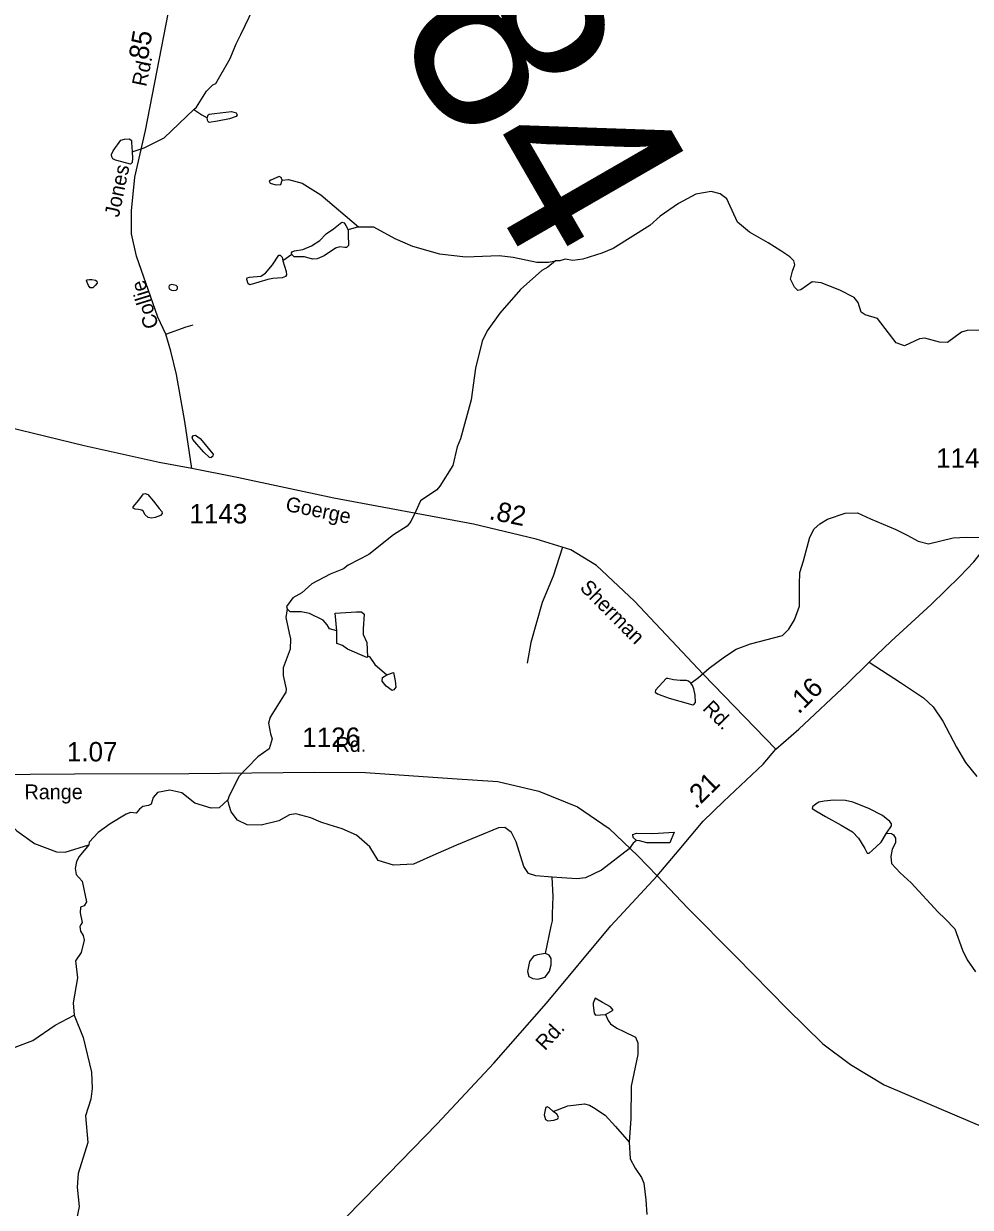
# Model space of a CAD drawing. Extents: x 2056842 to 2160602, y 826753 to 1016856.
# Drawn here: x 2065901 to 2071991, y 926037 to 933655 of the extents above; entities that cross this region are included whole.
import ezdxf

# ---------------------------------------------------------------- set-up
doc = ezdxf.new("R2010")
doc.units = 0
for name, color, linetype in [('Exist Hydrographic Creek Single Shore', 7, 'Continuous'), ('Exist Hydrographic Misc Water Feature', 7, 'Continuous'), ('Exist Road Non-System Type 51', 7, 'Continuous'), ('Exist Road Secondary Mileage Hundredths English Label', 7, 'Continuous'), ('Exist Road Secondary Structure Standard Bridge Number Label', 7, 'Continuous'), ('Exist Road Secondary Type 51 Attributed', 7, 'Continuous'), ('Exist Road Secondary Type 51 Label', 7, 'Continuous'), ('Exist Road Secondary Type 51 Number Label', 7, 'Continuous')]:
    doc.layers.add(name, color=color, linetype=linetype)

msp = doc.modelspace()

# ---------------------------------------------------------------- linework, layer by layer
at = {"layer": 'Exist Hydrographic Creek Single Shore'}
for points in [[(2072086.4, 931682.3), (2071970.5, 931680.1), (2071934.5, 931668.1), (2071844.5, 931602), (2071792.7, 931605.7), (2071698.7, 931629.7), (2071664.5, 931625.8), (2071566.8, 931581.5), (2071514.7, 931601.3), (2071394.2, 931757.1), (2071314.3, 931781), (2071288.4, 931797), (2071270.1, 931861), (2071244.1, 931892.7), (2071150.7, 931938.6), (2071031.8, 931986), (2070974.2, 931992.4), (2070901.4, 931940.5), (2070880.9, 931936.7), (2070859.2, 931959.7), (2070833.8, 932010.2), (2070846.4, 932061.5), (2070863, 932101.8), (2070856.6, 932128), (2070831.1, 932154.9), (2070772.2, 932193.3), (2070691.6, 932244.5), (2070571.4, 932313.6), (2070493.3, 932377.6), (2070435.2, 932503.4), (2070424.8, 932527.3), (2070380.9, 932559.4), (2070324.7, 932575), (2070224.9, 932557), (2070113.1, 932496.7), (2069995.3, 932416.4), (2069929.4, 932356.4), (2069693.7, 932208.1), (2069621.5, 932177.7), (2069497.7, 932139.6), (2069433.8, 932131.4), (2069385.8, 932139.3), (2069349.8, 932127.2), (2069321.9, 932127.2)], [(2069321.9, 932127.2), (2069273.8, 932087.1), (2069234, 932067), (2069098.2, 931942.8), (2068964.4, 931790.7), (2068882.7, 931678.5), (2068850.8, 931610.3), (2068807.2, 931438.2), (2068779.3, 931234.4), (2068712.1, 930982.1), (2068690, 930930.1), (2068662.2, 930810.2), (2068578.5, 930678.1), (2068558.6, 930653.9), (2068454.8, 930583.8), (2068424.8, 930517.5), (2068392.9, 930449.6), (2068369, 930421.5), (2068281.2, 930365.3), (2068121.4, 930239), (2067989.4, 930168.9), (2067959.7, 930144.9), (2067873.7, 930112.5), (2067755.6, 930048.4), (2067689.8, 929992.3), (2067632, 929960), (2067592.1, 929904.1), (2067596, 929888.3)], [(2070194, 929410.5), (2070242.6, 929446.3), (2070310.8, 929507.3), (2070410.2, 929579.4), (2070484.4, 929629.4), (2070577.8, 929663.9), (2070783.1, 929717.1), (2070822.7, 929758), (2070859.8, 929818.2), (2070893.1, 929905.2), (2070893.1, 930044.7), (2070893.6, 930122.4), (2070917.4, 930198.5), (2070959.2, 930350.5), (2070987.1, 930402.6), (2071023, 930436.6), (2071072.8, 930464.7), (2071186.7, 930503.6), (2071264.7, 930506.2), (2071349.2, 930467.8), (2071512.9, 930398.7), (2071585.8, 930361.6), (2071656.2, 930323.2), (2071722.5, 930307.8), (2071881.1, 930344.9), (2071965.5, 930348.8), (2072219.2, 930342.8)], [(2067596, 929888.3), (2067588, 929832), (2067608.2, 929732.1), (2067618.3, 929696.2), (2067616.6, 929628.3), (2067570.8, 929508.1), (2067570.8, 929460.2), (2067590.9, 929372.2), (2067586.9, 929352.3), (2067487.4, 929191.9), (2067475.5, 929151.8), (2067489.5, 929083.9), (2067499.6, 929051.8), (2067481.6, 928987.9), (2067407.6, 928936), (2067337.9, 928863.6), (2067285.9, 928809.5), (2067222.2, 928679.6), (2067214.2, 928659.4)], [(2067214.2, 928659.4), (2067158.3, 928607.4), (2067106.5, 928605.2), (2067002.2, 928637.4), (2066919, 928705.2), (2066841, 928720.6), (2066762.9, 928706.5), (2066733.5, 928674.5), (2066722, 928632.2), (2066704.1, 928623.3), (2066668.3, 928616.9), (2066646.5, 928599), (2066624.8, 928573.4), (2066589, 928578.5), (2066560.8, 928567), (2066458.2, 928504.2), (2066380.7, 928449.9), (2066322.9, 928385.8), (2066320.9, 928369.8)], [(2065452.5, 928668.4), (2065560.6, 928664.6), (2065672.7, 928632.7), (2065716.6, 928604.8), (2065856.9, 928459.1), (2065971.1, 928379.3), (2066113.2, 928325.5), (2066169.2, 928321.6), (2066321.1, 928370)], [(2066320.9, 928369.8), (2066259, 928293.6), (2066241.3, 928261.5), (2066233.1, 928217.7), (2066239.7, 928179.1), (2066278.1, 928135.6), (2066305, 928003.7), (2066289.6, 927976.9), (2066266.6, 927969.2), (2066264, 927932.1), (2066278.1, 927869.3), (2066270.4, 927859.1), (2066262.7, 927843.7), (2066266.6, 927813), (2066284.5, 927786.1), (2066290.9, 927755.4), (2066270.4, 927677.3), (2066234.6, 927623.6), (2066248.4, 927513.9), (2066218.8, 927353.7), (2066227, 927273.8)], [(2066227, 927273.8), (2066283.1, 927129.9), (2066337.5, 926905.9), (2066341.9, 926801.8), (2066334, 926733.7), (2066298.2, 926625.9), (2066314.4, 926453.9), (2066252.8, 926253.7), (2066245.1, 926165.6), (2066257.3, 926041.6), (2066231.6, 925913.9)]]:
    msp.add_lwpolyline(points, dxfattribs=at)
at = {"layer": 'Exist Hydrographic Misc Water Feature'}
for p, q in [((2068055.7, 932347.1), (2067988.5, 932327.7)), ((2067626.5, 932169), (2067568.9, 932128))]:
    msp.add_line(p, q, dxfattribs=at)
for points in [[(2066996.4, 933101.1), (2067012.4, 933117.1), (2067078, 933221.1), (2067118, 933261.2), (2067138, 933269.3), (2067229.7, 933429.5), (2067267.4, 933525.5), (2067299.4, 933585.6), (2067379, 933753.8)], [(2066598.7, 932829.1), (2066676.7, 932856.5), (2066804.6, 932920.6), (2066996.4, 933101.1)], [(2066996.4, 933101.1), (2067047.9, 933066.9), (2067082.6, 933049.5)], [(2067082.6, 933049.5), (2067088.4, 933066.9), (2067094.2, 933072.7), (2067129, 933075.6), (2067237.7, 933088.6), (2067268.1, 933079.9), (2067273.9, 933066.9), (2067268.1, 933056.7), (2067226.1, 933042.2), (2067147.8, 933026.3), (2067094.2, 933019.1), (2067087, 933027.7), (2067084.1, 933036.4), (2067082.6, 933049.5)], [(2066598.7, 932829.1), (2066601.6, 932788.5), (2066600.2, 932761), (2066588.6, 932750.8), (2066565.4, 932756.6), (2066492.9, 932776.9), (2066474.1, 932785.6), (2066468.3, 932797.2), (2066466.9, 932813.2), (2066477, 932836.4), (2066526.3, 932904.5), (2066549.4, 932911.8), (2066582.8, 932913.2), (2066594.4, 932903.1), (2066594.4, 932890), (2066598.7, 932829.1)], [(2067565.2, 932648.1), (2067557, 932664.1), (2067545.1, 932672), (2067491.1, 932648)], [(2067565.2, 932648.1), (2067605, 932652.2), (2067693.1, 932628.3), (2067813.3, 932552.6), (2068055.7, 932347.1)], [(2067491.1, 932648), (2067481.1, 932640), (2067487, 932628), (2067523.1, 932618.1)], [(2067523.1, 932618.1), (2067555.1, 932620.1), (2067565.2, 932648.1)], [(2067626.5, 932169), (2067625.2, 932180.5), (2067629, 932186.9), (2067643.1, 932192), (2067696.8, 932201), (2067753.1, 932225.3), (2067805.6, 932258.6), (2067846.5, 932302.1), (2067893.8, 932334.1), (2067948.8, 932376.4), (2067962.9, 932372.5), (2067973.1, 932354.6), (2067988.5, 932327.7)], [(2068055.7, 932347.1), (2068151.6, 932347.2), (2068289.8, 932271.6), (2068401.8, 932221.7), (2068575.9, 932174.1), (2068745.9, 932154.4), (2068959.9, 932162.8), (2069050, 932150.9), (2069202.1, 932119.2), (2069278, 932119.3), (2069322.1, 932127.4)], [(2067988.5, 932327.7), (2067988.5, 932297), (2067991.1, 932227.9), (2067978.3, 932213.8), (2067968, 932213.8), (2067934.8, 932217.6), (2067907.9, 932210), (2067835, 932161.3), (2067790.2, 932140.8), (2067759.5, 932139.6), (2067707.1, 932153.6), (2067675.1, 932154.9), (2067640.5, 932154.9), (2067632.9, 932162.6), (2067626.5, 932169)], [(2067568.9, 932128), (2067589.4, 932058.9), (2067591.9, 932037.2), (2067585.5, 932028.2), (2067565.1, 932018), (2067504.9, 932014.1), (2067471.7, 932009), (2067356.5, 931973.2), (2067345, 931980.8), (2067336.1, 932009), (2067339.9, 932019.2), (2067354, 932023.1), (2067426.9, 932029.5), (2067457.6, 932048.7), (2067501.1, 932102.4), (2067542, 932163.9), (2067551, 932163.9), (2067563.8, 932151.1), (2067568.9, 932128)], [(2066339.6, 932008), (2066364.4, 932003.9), (2066372.6, 931997.7), (2066373.6, 931985.3), (2066362.3, 931969.8), (2066345.8, 931955.4), (2066329.3, 931955.4), (2066317.9, 931968.8), (2066312.7, 931984.3), (2066306.5, 931999.8), (2066310.7, 932004.9), (2066324.1, 932008), (2066339.6, 932008)], [(2066862.9, 931974), (2066852.6, 931976), (2066837.1, 931969.8), (2066835, 931960.5), (2066838.1, 931947.1), (2066851.6, 931939.9), (2066865, 931936.8), (2066882.5, 931939.9), (2066891.8, 931948.1), (2066890.8, 931960.5), (2066881.5, 931968.8), (2066862.9, 931974)], [(2067059.7, 930956.3), (2067096.1, 930911.9), (2067120.1, 930883.4), (2067117.5, 930871.9), (2067105, 930859.4), (2067097, 930863), (2067059.7, 930896.8), (2067014.4, 930947.4), (2066988.6, 930977.7), (2066986, 930992.8), (2066994, 931003.4), (2067006.4, 931006.1), (2067036.6, 930984.8), (2067059.7, 930956.3)], [(2066736.2, 930581.7), (2066773.5, 930533.7), (2066789.5, 930515.9), (2066792.1, 930501.7), (2066780.6, 930489.2), (2066747.7, 930476.8), (2066723.7, 930471.4), (2066702.4, 930476.8), (2066681.1, 930496.3), (2066671.3, 930515.9), (2066662.4, 930523.9), (2066640.2, 930528.3), (2066618, 930530.1), (2066604.7, 930537.2), (2066604.7, 930544.3), (2066641.1, 930587), (2066673.1, 930628.8), (2066683.7, 930630.6), (2066700.6, 930623.4), (2066736.2, 930581.7)], [(2067916.4, 929747), (2067868.4, 929760.8), (2067854.5, 929784.8), (2067828.3, 929814.7), (2067740.3, 929858.5), (2067686.4, 929868.4), (2067616.2, 929868.3), (2067596.1, 929888.2)], [(2067916.4, 929747), (2067904.3, 929860.9), (2068042.1, 929869.1)], [(2068042.1, 929869.1), (2068074.1, 929869.2), (2068092.4, 929855.2), (2068084.4, 929759.3), (2068084.6, 929723.3), (2068108.6, 929671.2), (2068112.9, 929579.3)], [(2068112.9, 929579.3), (2068108.8, 929575.3), (2067984.7, 929629), (2067952.7, 929652.9), (2067916.6, 929664.9), (2067916.4, 929747)], [(2068112.9, 929579.3), (2068124.8, 929583.3), (2068160.8, 929531.3), (2068236.9, 929463.5)], [(2068233, 929391.5), (2068207, 929423.5), (2068209, 929447.5), (2068236.9, 929463.5)], [(2068236.9, 929463.5), (2068281, 929479.6), (2068291.1, 929425.6)], [(2068291.1, 929425.6), (2068295, 929383.6), (2068283.1, 929367.6), (2068271.2, 929363.6), (2068233, 929391.5)], [(2070194, 929410.5), (2070178.6, 929423.3), (2070165.8, 929427.1), (2070123.6, 929427.1), (2070081.4, 929431), (2070045.6, 929441.2), (2070035.3, 929439.9), (2069965, 929365.7), (2069963.7, 929352.9), (2069979.1, 929341.4), (2070007.2, 929329.8), (2070054.5, 929313.2), (2070176.1, 929278.6), (2070204.2, 929271), (2070213.2, 929273.5), (2070223.4, 929286.3), (2070220.8, 929333.7), (2070213.2, 929374.6), (2070204.2, 929395.1), (2070194, 929410.5)], [(2069300.2, 928160.5), (2069195.3, 928169.4), (2069149.2, 928185.2), (2069119.3, 928229.3), (2069070, 928389.7), (2069040.5, 928448.5), (2068995.8, 928480.6), (2068956.1, 928479.3), (2068686.2, 928366.6), (2068532.7, 928301.3), (2068409.9, 928245), (2068279.4, 928238.6), (2068180.9, 928269.3), (2068127.3, 928357.7), (2068042.9, 928431.2), (2067950.9, 928473.1), (2067866.3, 928498.5), (2067812.6, 928516.4), (2067748.6, 928543.3), (2067651.1, 928569.5), (2067611.5, 928563.1), (2067543.7, 928524.7), (2067429.8, 928496.6), (2067339, 928497.8), (2067276.3, 928528.6), (2067236.6, 928581), (2067222.5, 928623.7), (2067214.5, 928659.7)], [(2071452.8, 928445.5), (2071483.1, 928492.7), (2071484.4, 928505.5), (2071472.8, 928520.8), (2071425.5, 928558), (2071337.2, 928602.8), (2071234.9, 928643.7), (2071187.6, 928654), (2071113.4, 928656.5), (2071050.7, 928651.4), (2071017.4, 928645), (2070999.5, 928633.5), (2070975.2, 928614.3), (2070973.9, 928604), (2070997, 928587.4), (2071059.6, 928551.6), (2071160.7, 928496.5), (2071233.6, 928454.3), (2071272, 928412), (2071311.7, 928346.7), (2071328.3, 928316), (2071339.8, 928316), (2071359, 928332.7), (2071416.6, 928387.7), (2071452.8, 928445.5)], [(2069842.7, 928396.6), (2069823, 928380.5), (2069797, 928344.5), (2069619.2, 928206.1), (2069515.2, 928157.9), (2069459.2, 928149.8), (2069363.3, 928157.7), (2069300.2, 928160.5)], [(2069842.7, 928396.6), (2069822.8, 928416.5), (2069820.7, 928436.5), (2069844.7, 928444.6), (2069948.7, 928442.7)], [(2069951, 928382.7), (2069911, 928382.6), (2069862.8, 928394.5), (2069842.7, 928396.6)], [(2069948.7, 928442.7), (2070086.7, 928451), (2070058.8, 928382.9), (2069951, 928382.7)], [(2071452.8, 928445.5), (2071484.7, 928441.6), (2071496.6, 928433.6), (2071510.6, 928413.6), (2071510.8, 928381.6), (2071488.8, 928341.6), (2071479, 928293.5), (2071484.9, 928249.7), (2071539.1, 928189.7), (2071609.7, 928125.3), (2071785, 927935.8), (2071827.2, 927894.9), (2071891.8, 927828.4), (2071940, 927692.4), (2071970.1, 927628.5), (2072024.2, 927552.6)], [(2069258, 927669.6), (2069294, 927845.5), (2069303.8, 927881.5), (2069303.8, 927925.6), (2069306.6, 928037.7), (2069300.2, 928160.5)], [(2069258, 927669.6), (2069206.8, 927662), (2069181.3, 927653), (2069154.4, 927618.4), (2069141.6, 927554.4), (2069150.6, 927521.2), (2069176.1, 927508.4), (2069209.4, 927504.5), (2069255.5, 927517.3), (2069283.6, 927555.7), (2069295.1, 927598), (2069293.8, 927638.9), (2069281, 927659.4), (2069258, 927669.6)], [(2069624.7, 927354.2), (2069578.8, 927382.1), (2069564.8, 927350.1), (2069564.8, 927336.1)], [(2069564.8, 927336.1), (2069571, 927286.1), (2069580.8, 927274.1), (2069645, 927278.2)], [(2069645, 927278.2), (2069693, 927306.3), (2069676.8, 927326.3), (2069624.7, 927354.2)], [(2065387.6, 926833.8), (2065401.9, 926844.3), (2065537.8, 926936.6), (2065697.8, 927004.8), (2065758.8, 927029), (2065845.8, 927067.4), (2065959.6, 927109.6), (2066104.1, 927209.5), (2066227.2, 927273.8)], [(2069645, 927278.2), (2069661, 927238.2), (2069677, 927218.2), (2069717, 927190.4), (2069761.1, 927168.4), (2069837.1, 927132.6), (2069853.3, 927094.6), (2069851.5, 927020.6), (2069809.9, 926816.6), (2069806.2, 926608.5), (2069796.3, 926456.5)], [(2069308.3, 926653.2), (2069281.5, 926676.3), (2069268.7, 926682.7), (2069259.7, 926678.8), (2069255.9, 926664.8), (2069249.5, 926631.5), (2069257.2, 926602), (2069272.5, 926594.4), (2069310.9, 926598.2), (2069337.7, 926605.9), (2069341.6, 926617.4), (2069330.1, 926635.3), (2069308.3, 926653.2)], [(2069308.3, 926653.2), (2069402, 926689.7), (2069510.1, 926701.9), (2069542.1, 926694), (2069568.1, 926680.1), (2069642.1, 926630.2), (2069708.4, 926556.3), (2069796.3, 926456.5)], [(2069796.3, 926456.5), (2069802.7, 926348.5), (2069834.9, 926288.5), (2069876.7, 926228.7), (2069890.9, 926192.7), (2069903.2, 926084.7), (2069910.7, 925989.5)]]:
    msp.add_lwpolyline(points, dxfattribs=at)
at = {"layer": 'Exist Road Non-System Type 51'}
for points in [[(2066815.7, 931656.1), (2066947.6, 931703.4), (2066991.9, 931717.2)], [(2069367.1, 930285.4), (2069307, 930099), (2069236.9, 929928.2), (2069163.3, 929671.2), (2069140.8, 929539)]]:
    msp.add_lwpolyline(points, dxfattribs=at)
at = {"layer": 'Exist Road Secondary Type 51 Attributed'}
for points in [[(2066982.3, 930791.8), (2066937.4, 931093.7), (2066883.5, 931395.6), (2066847.6, 931546.5), (2066815.7, 931656.1), (2066765, 931765.7), (2066626.8, 932159.2), (2066594.4, 932303), (2066594.4, 932450.3), (2066616, 932665.9), (2066684.2, 932967.8), (2066905.1, 934105.2), (2067009.2, 934568.8), (2067118.8, 935156.4)], [(2071341.1, 929545.7), (2071482.1, 929681.4), (2071738.9, 929916.7), (2071924.7, 930097.3), (2072014.5, 930190.8), (2072095.3, 930293.2), (2072147.4, 930393.8), (2072200.3, 930516.9), (2072275.8, 930815.2), (2072336.8, 931041.6), (2072381.7, 931154.8), (2072447.2, 931252.7), (2072556.8, 931369.5), (2072745.9, 931499.8), (2072732.7, 931495.3), (2072883.6, 931622.9), (2073075.6, 931813.7), (2073106.3, 931840.2), (2073135.2, 931865.4), (2073217.1, 931927.2), (2073296.5, 931976.4), (2073350.7, 932009.1), (2073449, 932064.6)], [(2066982.3, 930791.8), (2066774, 930831.3), (2066290.1, 930938.3), (2065796.3, 931058.7), (2065415.6, 931157.5), (2065333.9, 931167.4)], [(2070740.1, 928984.6), (2070271.8, 929467.5), (2069830.1, 929938.3), (2069585.9, 930168.3), (2069420.7, 930268.9), (2069198.1, 930337.2), (2068794.1, 930432.4), (2067896.3, 930601.4), (2067275, 930734.3), (2066982.3, 930791.8)], [(2070740.1, 928984.6), (2070888.6, 929114.5), (2071199.3, 929405.5), (2071341.1, 929545.7)], [(2071341.1, 929545.7), (2071541.8, 929415), (2071689.4, 929315.3), (2071752.5, 929258), (2071814.8, 929165.2), (2071901.6, 928999.2), (2071960.8, 928898.5), (2072033.8, 928809.6)], [(2069975.6, 928171.1), (2070117.4, 928338.2), (2070273.2, 928522.8), (2070403.4, 928647.7), (2070657.9, 928888), (2070740.1, 928984.6)], [(2064536.7, 928802.7), (2064725.4, 928808.6), (2065370, 928821.2), (2066227.5, 928825.7), (2066962.8, 928828.4), (2067772.6, 928837.4), (2068100.3, 928834.7), (2068658.8, 928797), (2068950.6, 928778.1), (2069214.5, 928715.2), (2069464.1, 928614.6), (2069667.9, 928475.3), (2069852.9, 928299.2), (2069975.6, 928171.1)], [(2067688.9, 925680.6), (2068091.1, 926092.1), (2068560.6, 926574.6), (2068926.9, 926964.5), (2069265.4, 927349.9), (2069677.5, 927848.6), (2069975.6, 928171.1)], [(2069975.6, 928171.1), (2070174.3, 927961.4), (2070484, 927649.6), (2070812.6, 927313.6), (2071043.4, 927088.1), (2071219.3, 926956.9), (2071436.6, 926824), (2071905.3, 926624.5), (2072233, 926487)]]:
    msp.add_lwpolyline(points, dxfattribs=at)

# ---------------------------------------------------------------- texts
at = {"layer": 'Exist Road Secondary Mileage Hundredths English Label'}
for s, rotation, p in [('.85', 80.35279, (2066691.1, 933370.7)), ('.82', 348.40444, (2068890.2, 930466.6)), ('.16', 44.89426, (2070887.5, 929206.4)), ('1.07', 0.10669, (2066179.6, 928906.1)), ('.21', 44.23699, (2070223.8, 928595.9))]:
    msp.add_text(s, height=125, rotation=rotation, dxfattribs=at).set_placement(p)
at = {"layer": 'Exist Road Secondary Structure Standard Bridge Number Label'}
msp.add_text('84', height=1230.31, rotation=300, dxfattribs=at).set_placement((2068267.5, 933626.2))
at = {"layer": 'Exist Road Secondary Type 51 Label'}
for s, rotation, p in [('Rd.', 78.16274, (2066689.3, 933245)), ('Jones', 78.16274, (2066513.3, 932404.3)), ('Collie', 107.10607, (2066771.5, 931708)), ('Goerge', 348.40444, (2067580.8, 930520)), ('Sherman', 314.81081, (2069473.6, 930018.8)), ('Rd.', 314.81081, (2070263.5, 929242.1)), ('Rd.', 0.10669, (2067907.4, 928967.9)), ('Range', 0.10669, (2065907, 928663.1)), ('Rd.', 47.2932, (2069254.6, 927041.2))]:
    msp.add_text(s, height=95, rotation=rotation, dxfattribs=at).set_placement(p)
at = {"layer": 'Exist Road Secondary Type 51 Number Label'}
for s, p in [('1141', (2071770.9, 930796.7)), ('1143', (2066967.6, 930438)), ('1126', (2067693.7, 928999.6))]:
    msp.add_text(s, height=125, dxfattribs=at).set_placement(p)

doc.saveas('drawing.dxf')
